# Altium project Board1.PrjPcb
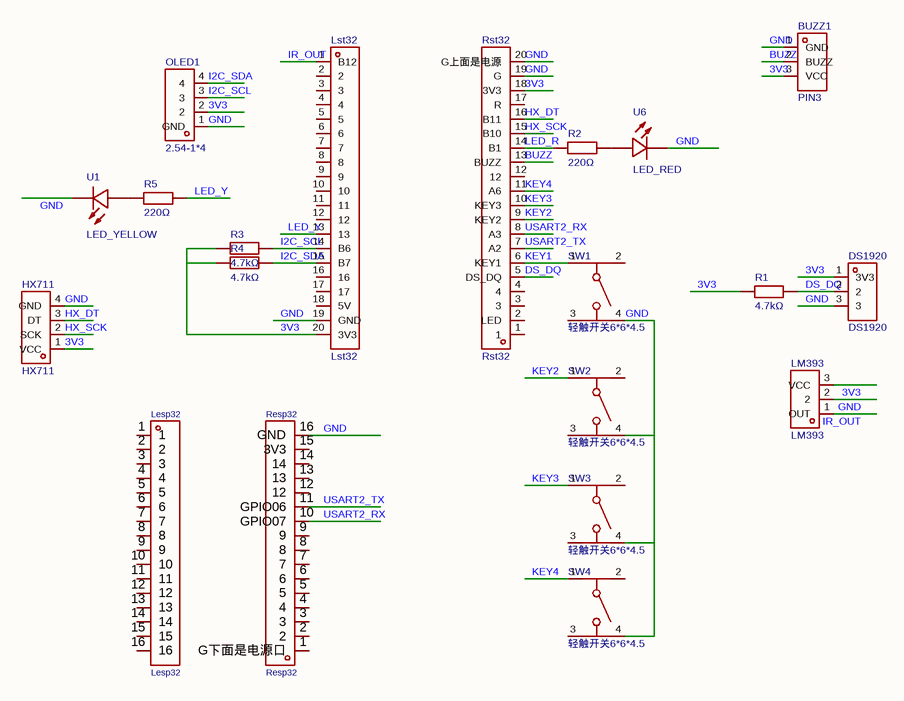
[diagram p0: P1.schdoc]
1 sheet, 20 parts. Net scope: global (net labels, ports and power ports of the same name join across sheets).
Board file: PCB1.pcbdoc

## Sheet P1.schdoc
size 297 x 209 mm; Symbol: Drawing-Symbol_A4; Device: Drawing-Symbol_A4; Company: 嘉立创EDA; Version: V1.0; Page Size: A4; @Project Name: 毕业设计2; @Update Date: 2026-10-22; @Create Date: 2026-10-22; @Board Name: Board1; @Page Name: P1; @Create Time: 13:47:32; @Page Count: 1; @Page No: 1; @Schematic Name: Schematic1; @Update Time: 13:47:32; @Assembly Variant: Basic; Border: 1; Title Block Position: 3; Size: A4; Width: 1170; Height: 825; Region Start: 1; X Region Count: 6; Y Region Count: 4; Blade Width: 10

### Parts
BUZZ1  PIN3  [HDR-TH_3P-P2.54-V-M-1]
DS1920  DS1920  [HDR-TH_3P-P2.54-V-M]
HX711  HX711  [HDR-TH_4P-P2.54-V-M-1]
Lesp32  Lesp32  [HDR-TH_1X16P]
LM393  LM393  [HDR-TH_3P-P2.54-V-M-1]
Lst32  Lst32  [HDR-TH_HMT-PM254-1X20Z-H85]
OLED1  2.54-1*4  [HDR-TH_4P-P2.54-V-M-1]
R1  4.7kΩ  [RES-TH_BD3.3-L9.0-P13.00-D0.6]
R2  220Ω  [RES-TH_BD3.3-L9.0-P13.00-D0.6]
R3  4.7kΩ  [RES-TH_BD3.3-L9.0-P13.00-D0.6]
R4  4.7kΩ  [RES-TH_BD3.3-L9.0-P13.00-D0.6]
R5  220Ω  [RES-TH_BD3.3-L9.0-P13.00-D0.6]
Resp32  Resp32  [HDR-TH_1X16P]
Rst32  Rst32  [HDR-TH_HMT-PM254-1X20Z-H85]
SW1  轻触开关6*6*4.5  [KEY-TH_4P-L6.0-W6.0-P4.50-LS7.5]
SW2  轻触开关6*6*4.5  [KEY-TH_4P-L6.0-W6.0-P4.50-LS7.5]
SW3  轻触开关6*6*4.5  [KEY-TH_4P-L6.0-W6.0-P4.50-LS7.5]
SW4  轻触开关6*6*4.5  [KEY-TH_4P-L6.0-W6.0-P4.50-LS7.5]
U1  LED_YELLOW  [LED-TH_BD4.0-P2.54-FD_RED]
U6  LED_RED  [LED-TH_BD4.0-P2.54-FD_RED]

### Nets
3V3: BUZZ1.3(VCC) DS1920.1(3V3) HX711.1(VCC) LM393.3(VCC) Lst32.20(3V3) OLED1.2 R1.1 R3.1 R4.1 Rst32.18(3V3)
BUZZ: BUZZ1.2(BUZZ) Rst32.13(BUZZ)
DS_DQ: DS1920.2 R1.2 Rst32.5(DS_DQ)
GND: BUZZ1.1(GND) DS1920.3 HX711.4(GND) LM393.2 Lst32.19(GND) OLED1.1(GND) Resp32.16(GND) Rst32.19(G) Rst32.20(G上面是电源) SW1.4 SW2.4 SW3.4 SW4.4 U1.2(-) U6.2(-)
HX_DT: HX711.3(DT) Rst32.16(B11)
HX_SCK: HX711.2(SCK) Rst32.15(B10)
I2C_SCL: Lst32.14(B6) OLED1.3 R3.2
I2C_SDA: Lst32.15(B7) OLED1.4 R4.2
IR_OUT: LM393.1(OUT) Lst32.1(B12)
KEY1: Rst32.6(KEY1) SW1.1
KEY2: Rst32.9(KEY2) SW2.1
KEY3: Rst32.10(KEY3) SW3.1
KEY4: Rst32.11(A6) SW4.1
LED_R: R2.1 Rst32.14(B1)
LED_Y: Lst32.13 R5.1
USART2_RX: Resp32.10(GPIO07) Rst32.8(A3)
USART2_TX: Resp32.11(GPIO06) Rst32.7(A2)
NetR2_2: R2.2 U6.1(+)
NetR5_2: R5.2 U1.1(+)

Not connected (* = marked no-connect by the designer): Lesp32 1 2 3 4 5 6 7 8 9 10 11 12 13 14 15 16; Lst32 2 3 4 5 6 7 8 9 10 11 12 16 17 18(5V); Resp32 1(G下面是电源口) 2 3 4 5 6 7 8 9 12 13 14 15(3V3); Rst32 1 2(LED) 3 4 12 17(R); SW1 2 3; SW2 2 3; SW3 2 3; SW4 2 3

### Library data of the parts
BUZZ1 LM393 = 2.54mm-1*3P 直针: 3D Model: 94a8ffe137b6410295cb18cd3ffd99db0819f05c4eef4c71ace90d822a990e87; 3D Model Transform: 299.9994,100,0,0,0,0,0,0,-118.11; AddInBom: yes; ModelName: HDR-M-2.54_1x3
DS1920 = 2.54MM间距单排插针3P/高度11mm: 3D Model: bb473b6d38ff42a99216a4fcdbdcc4cb0819f05c4eef4c71ace90d822a990e87; 3D Model Transform: 300.03877,100,0,0,0,0,0,0,-118.11; AddInBom: yes; ModelName: HDR-TH_3P-P2.54-M-LI-1X3P
HX711 OLED1 = 2.54-1*4: 插针结构:1x4P;间距:2.54mm;圆针/方针:方针;安装方式:直插;排数:单排;总PIN位数:4P;额定电流:2.5A;配合针长度:6mm;塑高:2.54mm;端接针长度:3mm;触头材质:黄铜;触头镀层:金;工作温度:-40℃~+105℃;; Manufacturer: ZHOURI(洲日); 3D Model: e2e03939c192453cba872779c0cb63900819f05c4eef4c71ace90d822a990e87; 3D Model Transform: 400.039,100,0,0,0,0,0,0,-118.11; Pin Structure: 1x4P; Pitch: 2.54mm; Circluar Pins/Square Pins: 方针; Current Rating: 2.5A; AddInBom: yes
Lesp32 Resp32 = 1*16P: AddInBom: yes
Lst32 Rst32 = HMT-PM254-1*20Z-H85: 插孔结构:1x20P;间距:2.54mm;圆孔/方孔:方孔;安装方式:直插;排数:单排;总孔位数:20P;额定电流:3A;插孔方向:顶部;塑高:8.5mm;触头材质:黄铜;触头镀层:金;工作温度:-40℃~+105℃;; Manufacturer: HMTCONN(华明通); 3D Model: b640e97081224ea7b4c96dfa3029874f0819f05c4eef4c71ace90d822a990e87; 3D Model Transform: 2019.681,94.882,0,0,0,0,0,0,-129.921; Holes Structure: 1x20P; Pitch: 2.54mm; Circular Hole / Square Hole: 方孔; Number of Positions: 20P; Current Rating: 3A; Holes Direction: 顶部; PIN Length: 3.2mm; AddInBom: yes
R1-R5 = RN1WS4.7KΩFT/BA1: 电阻类型:金属膜电阻;阻值:4.7kΩ;精度:±1%;功率:1W;温度系数:±50ppm/℃;; Manufacturer: Tyohm(幸亚电阻); 3D Model: ba6d6a4d684e4c9c99cd35ba00f099d90819f05c4eef4c71ace90d822a990e87; 3D Model Transform: 535.432,129.82565,0,0,0,0,0,0,-196.85; Tolerance: ±1%; Power(Watts): 1W; AddInBom: yes
SW1-SW4 = 轻触开关6*6*4.5: 材质： 无卤; 3D Model: 84d39232fe0a426fa95ea2653754a6e50819f05c4eef4c71ace90d822a990e87; 3D Model Transform: 306.868,236.22,0,0,0,0,0,0,-118.11; AddInBom: yes; ModelName: KEY-TH_4P-L6.0-W6.0-H4.5-LS6.5-P4.5
U1 U6 = LED: Symbol: LED_C9900015665; 3D Model: 08d245f9ade94e79a608b24242b3e8900819f05c4eef4c71ace90d822a990e87; 3D Model Transform: 137.561,157.46465,0,0,0,0,-8.858,0,-196.85; AddInBom: yes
